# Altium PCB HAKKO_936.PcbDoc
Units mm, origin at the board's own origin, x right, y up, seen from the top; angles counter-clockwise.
Board outline 100 x 73 mm, 2 copper layers (Top Layer, Bottom Layer); 42 components, 27 nets, 110 pads, 10 vias.
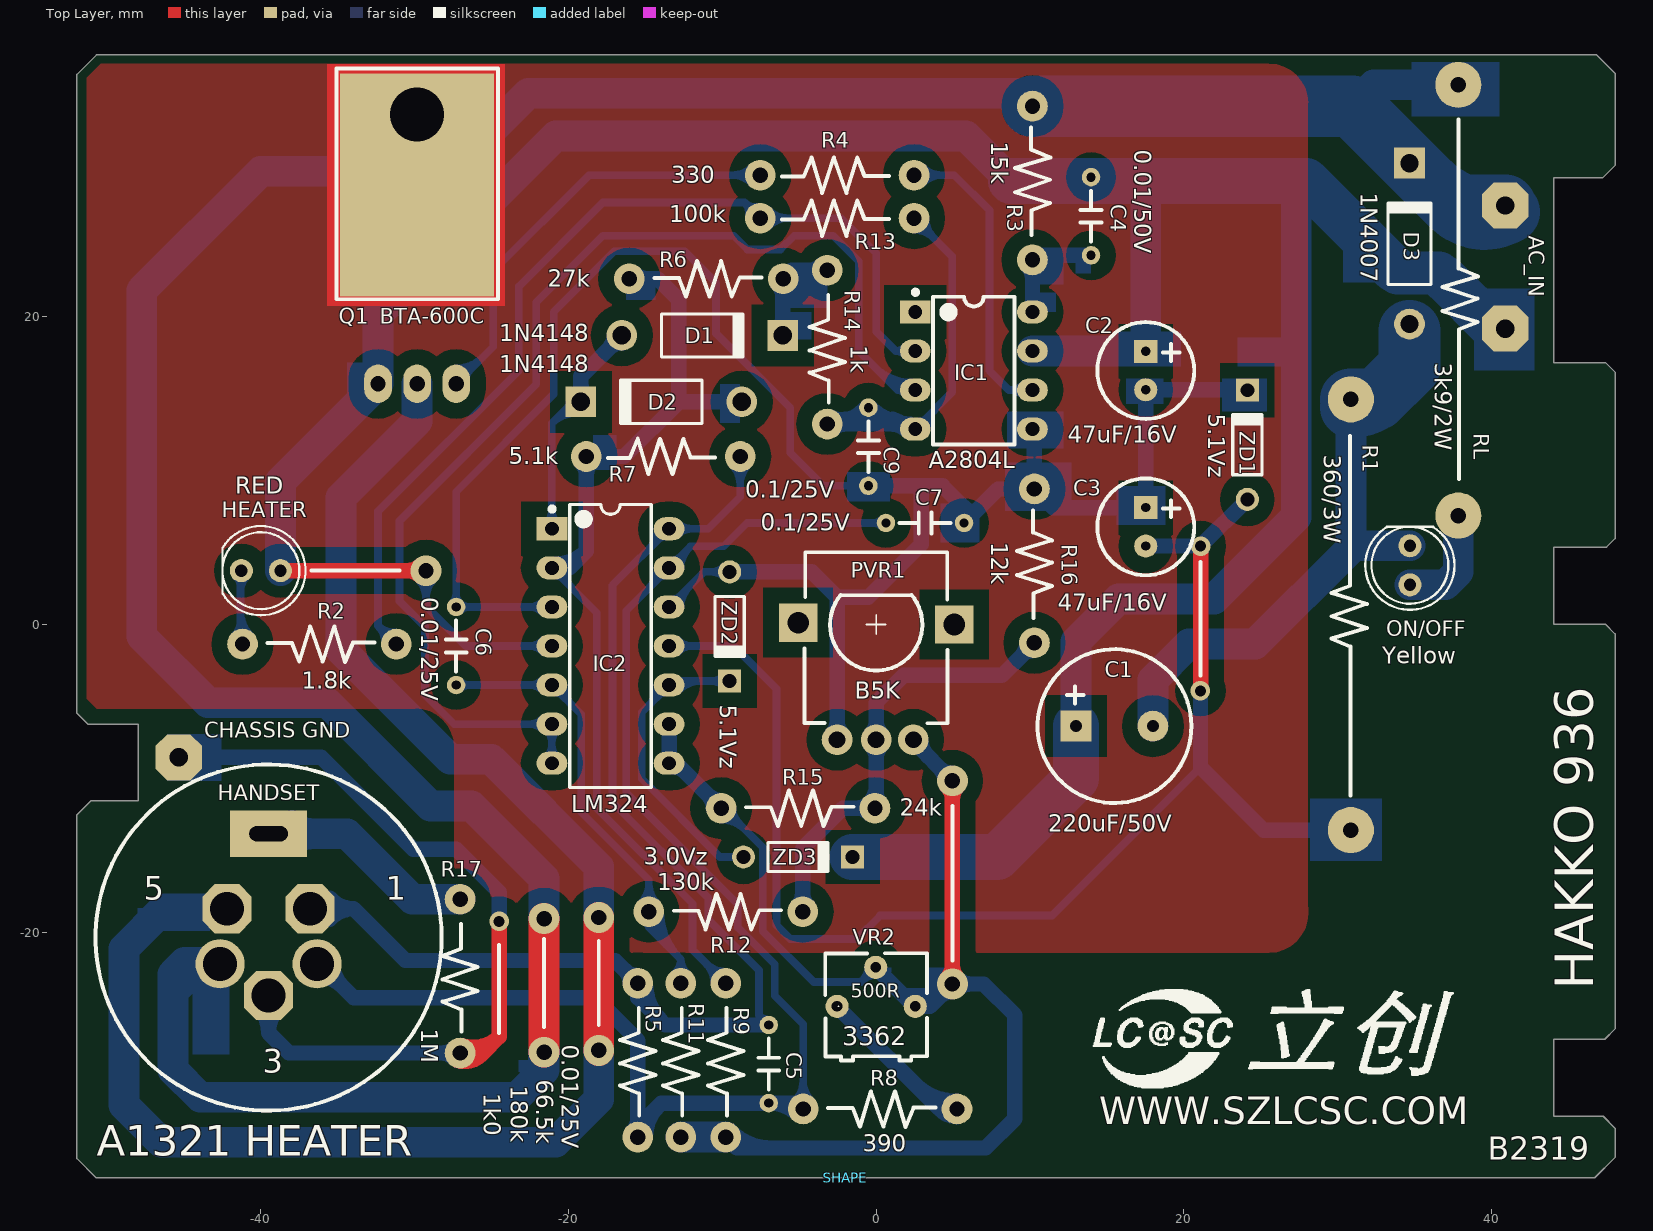
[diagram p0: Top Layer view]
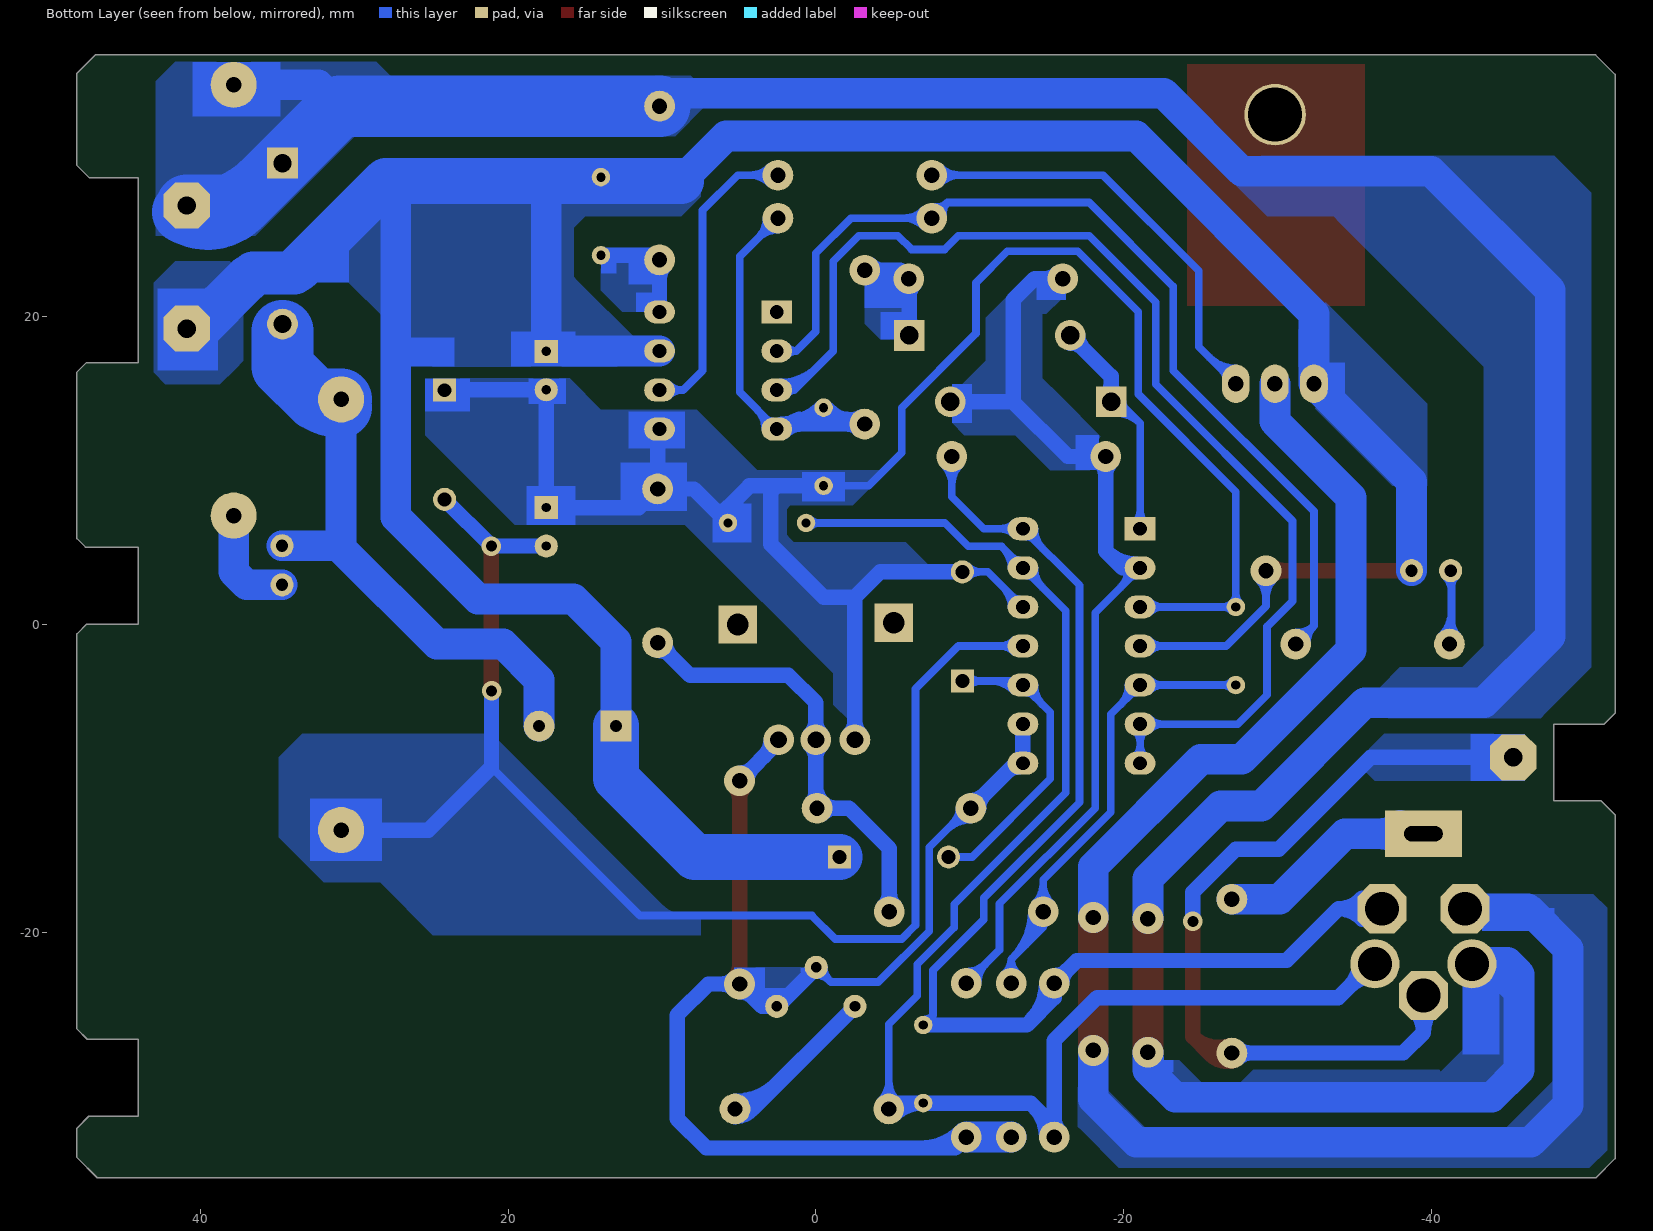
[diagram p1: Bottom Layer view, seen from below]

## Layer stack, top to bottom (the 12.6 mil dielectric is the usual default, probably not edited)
Top Layer: signal copper 0.0356
Dielectric: dielectric 0.32, FR-4, Dk 4.8
Bottom Layer: signal copper 0.0356

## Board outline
-51.962,-34.724 -51.962,-12.372 -51.059,-11.469 -47.962,-11.469 -47.962,-6.469 -51.261,-6.469 -51.962,-5.768 -51.962,35.761 -50.692,37.031 46.844,37.031 48.038,35.837 48.038,29.843 47.226,29.031 44.038,29.031 44.038,17.031 47.413,17.031 48.038,16.406 48.038,5.586 47.483,5.031 44.038,5.031 44.038,0.031 47.395,0.031 48.038,-0.612 48.038,-26.291 47.36,-26.969 44.038,-26.969 44.038,-31.969 47.264,-31.969 48.038,-32.743 48.038,-34.648 46.717,-35.969 -50.717,-35.969

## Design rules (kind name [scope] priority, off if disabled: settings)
Clearance Clearance_1 [InPolygon] p1 off: gap=1
Clearance [All] p2: gap=0.254
ComponentClearance [All] p1 off: gap=0.254 collisioncheckmode=3 verticalgap=0.254 showdistances=FALSE
Height [All] p1 off: minheight=0 maxheight=25.4 prefheight=12.7
PolygonConnect [All] p1: connectstyle=Relief reliefconductorwidth=0.254 reliefentries=4 polygonreliefangle="90 Angle" airgapwidth=0.254
RoutingVias [All] p1: holewidth=0.711 width=1.27 viastyle="Through Hole" minholewidth=0.711 minwidth=1.27 maxholewidth=3 maxwidth=5
SolderMaskExpansion [All] p1: expansion=0.102
Width [All] p1: maxlimit=10 minlimit=0.254 preferedwidth=0.254
26 further rules are at their usual default settings.

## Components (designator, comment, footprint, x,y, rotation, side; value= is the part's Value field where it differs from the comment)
AC_IN "24VAC" AC_IN 40.894,23.241 r270 top
C1 "220uF/50V" CAP_POL_5mm 15.494,-6.604 r0 top
C2 "47uF/16V" CAP_POL_2.5mm 17.526,16.51 r270 top
C3 "47uF/16V" CAP_POL_2.5mm 17.526,6.35 r270 top
C4 "0.01uF/50V" CAP_5.05mm 13.97,26.543 r270 top
C5 "0.01uF/25V" CAP_5.05mm -6.985,-28.575 r270 top
C6 "0.01uF/25V" CAP_5.05mm -27.305,-1.397 r270 top
C7 "0.1uF/25V" CAP_5.05mm 3.175,6.604 r180 top
C9 "0.01uF/25V" CAP_5.05mm -0.508,11.557 r90 top
"CHASSIS GND" "CHASSIS GND" CHASSIS_GND -45.339,-8.636 r90 top
D1 "1N4148" DO-41 -11.303,18.796 r0 top
D2 "1N4148" DO-41 -13.97,14.478 r180 top
D3 "1N4007" DO-41 34.671,24.765 r90 top
HANDSET "HANDSET SOCKET" "HANDSET - metal" -39.5,-20.35 r0 top
HEATER "LED_RED" LED -40,3.5 r180 top locked
IC1 "uPC1701C/KA2804" uPC1701C 6.35,16.51 r0 top
IC2 "uPC324" UPC324C -17.272,-1.397 r0 top
ON/OFF "LED_RED" LED 34.7,3.85 r90 top locked
PVR1 "TEMP CTRL" RK09L1140A65 0,0 r0 top locked
Q1 "NEC AC05D 5A TRIAC" TRIAC -29.845,33.147 r0 top locked
R1 "360/5W" RES_2W 30.861,0.635 r90 top
R2 "1K8" RES_1/4W -36.195,-1.27 r180 top
R3 "15K" RES_1/4W 10.16,28.702 r270 top
R4 "330" RES_1/4W -2.54,29.21 r0 top
R5 "1K0 1%" RES_1/4W -15.494,-28.321 r90 top
R6 "27K 1%" RES_1/4W -11.049,22.479 r180 top
R7 "5K1 1%" RES_1/4W -13.843,10.922 r0 top
R8 "390 1%" RES_1/4W 0.254,-31.496 r180 top
R9 "66K5 1%" RES_1/4W -9.779,-28.321 r90 top
R11 "180K 1%" RES_1/4W -12.7,-28.321 r90 top
R12 "130K 1%" RES_1/4W -9.779,-18.669 r180 top
R13 "100K" RES_1/4W -2.54,26.416 r0 top
R14 "1K0" RES_1/4W -3.175,18.034 r90 top
R15 "24K0" RES_1/4W -5.08,-11.938 r180 top
R16 "1K2" RES_1/4W 10.287,3.81 r270 top
R17 "1M0 5%" RES_1/4W -27.051,-22.86 r90 top
RL "3K9 2W" RES_2W 37.846,21.082 r270 top
SHAPE "Comment" BOARD_SHAPE -2,-35.969 r0 top locked
VR2 "CALCTRL" Bournes_3362P 0,-24.9 r0 top locked
ZD1 "5.1Vz 500mW" DO-35 24.13,11.684 r90 top
ZD2 "5.1Vz 500mW" DO-35 -9.525,-0.127 r270 top
ZD3 "3.0Vz 500mW" DO-35 -5.08,-15.113 r0 top

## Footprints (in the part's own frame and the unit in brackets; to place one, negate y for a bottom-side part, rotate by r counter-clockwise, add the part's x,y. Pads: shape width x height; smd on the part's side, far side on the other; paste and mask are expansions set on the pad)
AC_IN [mm]
  oct 3x3 hole 1.2: 1(-4,0) 2(4,0)
BOARD_SHAPE [mm]
Bournes_3362P [mm]
  round 1.5 hole 0.7: 1(2.54,0.076) 2(-2.54,0.076) 3(-0.03,2.612)
  silkscreen extent -3.31,-3.45 3.3,3.53, body extent -3.3,-3.45 3.3,3.53, height 4.7
CAP_5.05mm [mm] "0.1uF 25V"
  round 1.2 hole 0.6: 1(-2.54,0) 2(2.54,0)
  silkscreen extent -1.65,-0.68 1.65,0.68
CAP_POL_2.5mm [mm]
  rect 1.5x1.5 hole 0.6: 1(-1.25,0)
  round 1.5 hole 0.6: 2(1.25,0)
  silkscreen extent -3.15,-3.15 3.15,3.15
CAP_POL_5mm [mm]
  rect 2x2 hole 0.8: 1(-2.5,0)
  round 2 hole 0.8: 2(2.5,0)
  silkscreen extent -5,-5 5,5
CHASSIS_GND [mm]
  oct 3x3 hole 1.2: 1(0,0)
DO-35 [mm] "Diode, Axial; Body 3.8 x 1.9 mm (LxDia. max), Lead Dia. 0.53 mm (max)"
  round 1.5 hole 0.9: A(-3.55,0)
  rect 1.5x1.5 hole 0.9: K(3.55,0)
  silkscreen extent -1.95,-0.95 2.05,0.95
DO-41 [mm] "Diode, Axial; Body 5.2 x 2.7 mm (LxDia. max), Lead Dia. 0.86 mm (max)"
  round 2 hole 1.2: A(-5.23,0)
  rect 2x2 hole 1.2: K(5.23,0)
  silkscreen extent -2.65,-1.4 2.75,1.4
"HANDSET - metal" [mm]
  oct 3.2x3.2 hole 2.2: 1(2.7,1.875) 3(0,-3.77) 5(-2.7,1.875)
  round 3.2 hole 2.2: 2(3.15,-1.71) 4(-3.15,-1.71)
  rect 5x3 hole 1 slot 2.5 at 0 deg: 6(0,6.75)
  silkscreen extent -11.25,-11.25 11.25,11.25
LED [mm]
  round 1.5 hole 0.8: A(-1.27,0) K(1.27,0)
  silkscreen extent -2.9,-2.9 2.5,2.9
RES_1/4W [mm]
  round 2 hole 1: 1(5,0) 2(-5,0)
  silkscreen extent -3.6,-1.15 3.38,1.16
RES_2W [mm]
  round 3 hole 1: 1(-14,0) 2(14,0)
  silkscreen extent -11.74,-1.04 11.61,1.27
RK09L1140A65 [mm]
  round 2 hole 1.1: 1(2.413,-7.493) 2(-2.54,-7.493) 3(0,-7.493)
  rect 2.5x2.5 hole 1.4: 4(-5.08,0.127) 4(5.08,0)
  silkscreen extent -4.66,-6.42 4.64,4.7, body extent -6.05,-7.65 6.05,4.85, height 35
TRIAC [mm]
  round 4 hole 3.5 unplated: 0(-0.01,0)
  rect 10x14.5 smd: 0(0,-4.56)
  oval 1.8x2.5 hole 1: G(2.54,-17.5) T1(-2.54,-17.5) T2(0,-17.5)
  silkscreen extent -5.25,-12 5.25,3
UPC324C [mm]
  rect 2x1.5 hole 0.9: 1(-3.81,7.62)
  oval 2x1.5 hole 0.9: 2(-3.81,5.08) 3(-3.81,2.54) 4(-3.81,0) 5(-3.81,-2.54) 6(-3.81,-5.08) 7(-3.81,-7.62) 8(3.81,-7.62) 9(3.81,-5.08) 10(3.81,-2.54) 11(3.81,0) 12(3.81,2.54) 13(3.81,5.08) 14(3.81,7.62)
  silkscreen extent -3.95,-9.2 2.65,9.2, body extent -3.94,-9.52 3.94,9.53, height 4.19
uPC1701C [mm]
  rect 2x1.5 hole 0.9: 1(-3.81,3.81)
  oval 2x1.5 hole 0.9: 2(-3.81,1.27) 3(-3.81,-1.27) 4(-3.81,-3.81) 5(3.81,-3.81) 6(3.81,-1.27) 7(3.81,1.27) 8(3.81,3.81)
  silkscreen extent -3.95,-4.8 2.65,5.24, body extent -3.93,-5.46 3.94,5.46, height 5.08

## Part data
AC_IN: library part 24VAC_IN, "POWER"
C1 C2 C3: library part "Cap Pol1", "Polarized Capacitor (Radial)"
C4 C5 C6 C7 C9: library part Cap, "Capacitor"
D1 D2 D3: library part Diode, "Default Diode"
HEATER ON/OFF: library part LED1, "Typical RED GaAs LED"
IC1: library part uPC1701C, "TRIAC DRIVER"
IC2: "Quar Amplifier"
PVR1 VR2: library part RPot, "Potentiometer"
Q1: library part Triac, "Silicon Bidirectional Triode Thyristor"
R1 R2 R3 R4 R5 R6 R7 R8 R9 R11 R12 R13 R14 R15 R16 R17 RL: library part "Res Semi", "Semiconductor Resistor"
ZD1 ZD2 ZD3: library part "D Zener", "Zener Diode"

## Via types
v1: diameter 2, hole 1, Top Layer to Bottom Layer, 7 vias
v2: diameter 1.27, hole 0.711, Top Layer to Bottom Layer, 3 vias

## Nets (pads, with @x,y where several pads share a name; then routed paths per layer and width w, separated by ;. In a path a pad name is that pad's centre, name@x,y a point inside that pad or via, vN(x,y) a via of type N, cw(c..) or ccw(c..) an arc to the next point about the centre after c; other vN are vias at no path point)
CHASSIS_GND: "CHASSIS GND.1" HANDSET.3 R17.2 | length 67.9
  Top Layer w1: R17.2@-27.201,-28.337 ccw(c-26.747,-26.894) -25.678,-27.964 ; R17.2 -25.574,-27.86 -24.511,-26.797 ; R17.2@-26.901,-27.383 ccw(c-26.189,-25.119) -24.511,-26.797 ; R17.2@-26.697,-28.214 cw(c-25.844,-29.067) -25.844,-27.86 cw(c-25.844,-26.653) R17.2@-26.697,-27.506 ; v2(-24.511,-19.304) -24.511,-26.797
  Bottom Layer w1: -45.339,-8.636 -36.068,-8.636 -30.099,-14.605 -27.305,-14.605 -24.511,-17.399 v2(-24.511,-19.304) ; -44.632,-9.343 cw(c-42.925,-11.05) -42.925,-8.636 cw(c-42.925,-6.222) -44.632,-7.929 ; HANDSET.3@-40.207,-24.807 cw(c-41.914,-26.514) -39.5,-26.514 cw(c-37.086,-26.514) HANDSET.3@-38.793,-24.807 ; HANDSET.3@-39.5,-24.1 -39.5,-26.54 -38.18,-27.86 R17.2 ; R17.2@-27.405,-28.214 ccw(c-28.258,-29.067) -28.258,-27.86 ccw(c-28.258,-26.653) R17.2@-27.405,-27.506
"CKT GND": C2.2 C3.1 C6.1 C7.1 C9.1 IC1.5 IC2.3 IC2.12 PVR1.2 R16.2 ZD1.K ZD2.A | length 152.1
  Bottom Layer w0.5: C6.1@-27.552,1.39 ccw(c-28.15,1.988) -27.305,1.988 ccw(c-26.46,1.988) -27.058,1.39 ccw(c-26.46,1.988) -26.46,1.143 ccw(c-26.46,0.298) C6.1@-27.058,0.896 ; IC2.3@-21.686,0.789 ccw(c-22.539,-0.064) -22.539,1.143 ccw(c-22.539,2.35) IC2.3@-21.686,1.497 ; IC2.3 C6.1 -27.305,8.636 -20.955,14.986 -20.955,20.32 -17.018,24.257 -12.446,24.257 -10.414,22.225 -10.414,18.923 -5.588,14.097 -5.588,11.176 -3.429,9.017 C9.1 ; IC2.12 -11.182,3.423 ZD2.A ; IC2.12@-13.212,1.643 ccw(c-13.212,2.247) -12.785,1.82 ; IC2.12@-12.712,1.143 cw(c-10.901,1.143) -12.182,2.423 ; ZD2.A@-9.879,3.069 ccw(c-10.732,2.216) -10.732,3.423 ccw(c-10.732,4.63) ZD2.A@-9.879,3.777 ; C9.1@-0.755,8.77 ccw(c-1.353,8.172) -1.353,9.017 ccw(c-1.353,9.862) C9.1@-0.755,9.264
  Bottom Layer w1: ZD2.A -4.185,3.423 -2.54,1.778 ; PVR1.2@-2.894,-7.139 ccw(c-3.747,-6.286) -2.54,-6.286 ccw(c-1.333,-6.286) PVR1.2@-2.186,-7.139 ; PVR1.2 -2.54,1.778 ; C9.1 2.794,9.017 ; 4.826,8.509 cw(c2.921,6.604) C7.1@5.615,6.604 ; R16.2@9.933,8.456 ccw(c9.08,7.603) 9.08,8.81 ccw(c9.08,10.017) 9.933,9.164 ccw(c9.08,10.017) 10.287,10.017 ccw(c11.494,10.017) R16.2@10.641,9.164 ; IC1.5 10.287,12.573 R16.2 ; R16.2@10.287,8.31 cw(c10.287,7.103) 11.141,7.956 cw(c11.994,8.81) R16.2@10.787,8.81 ; 10.287,11.799 cw(c11.311,11.799) IC1.5@10.587,12.523 ; ZD1.K 24.104,15.26 C2.2 C3.1 11.497,7.6 R16.2 ; -2.54,1.778 -0.508,1.778 2.921,5.207 2.921,8.636 2.794,8.763 2.794,9.017 ; 2.794,9.017 4.318,9.017 5.715,7.62 C7.1 7.921,8.81 R16.2
HEATER1: HANDSET.5 Q1.T2 | length 107.5
  Top Layer w2: v1(-18.034,-27.686) v1(-18.034,-19.05)
  Bottom Layer w2: HANDSET.5@-42.748,-18.475 -46.288,-18.475 -48.895,-21.082 -48.895,-31.242 -46.482,-33.655 -20.828,-33.655 -18.034,-30.861 v1(-18.034,-27.686) ; Q1.T2 -29.845,13.208 -34.798,8.255 -34.798,-1.651 -27.686,-8.763 -25.019,-8.763 -18.034,-15.748 v1(-18.034,-19.05)
HEATER2: AC_IN.1 D3.K HANDSET.4 R3.2 RL.1 | length 224.1
  Top Layer w2: v1(-21.59,-27.813) v1(-21.59,-19.117)
  Bottom Layer w2: -45.259,-23.415 cw(c-42.748,-25.927) HANDSET.4@-42.748,-22.375 ; HANDSET.4@-42.748,-21.975 -44.962,-21.975 -45.72,-22.733 -45.72,-28.956 -43.942,-30.734 -23.368,-30.734 -21.59,-28.956 v1(-21.59,-27.813) cw(c-24.349,-27.813) -22.398,-29.764 ; v1(-21.59,-19.117) -21.59,-16.51 -26.304,-11.796 -28.971,-11.796 -35.687,-5.08 -43.434,-5.08 -47.752,-0.762 -47.752,21.717 -40.005,29.464 -27.686,29.464 -22.606,34.544 9.318,34.544 R3.2 ccw(c8.127,31.669) 8.127,34.544 ; 30.964,33.702 32.344,35.082 RL.1
  Bottom Layer w4: R3.2 30.964,33.702 D3.K 37.425,27.241 ; 35.826,28.84 ccw(c40.894,33.909) AC_IN.1@40.894,26.741 ; AC_IN.1 37.425,27.241 ; AC_IN.1@41.159,26.817 cw(c39.558,29.374) 37.425,27.241
NetC1_2: C1.2 D3.A ON/OFF.K R1.2 | length 41.9
  Bottom Layer w2: C1.2 17.994,-3.596 20.32,-1.27 24.638,-1.27 30.861,4.953 ; 30.861,5.12 R1.2 ; 31.028,5.12 ON/OFF.K
  Bottom Layer w4: R1.2@30.861,14.135 ccw(c30.861,16.986) 32.877,14.97 ; R1.2 32.542,14.635 34.671,16.764 D3.A@34.671,19.106
NetC4_2: C4.2 IC1.8 R3.1 | length 11
  Bottom Layer w1: R3.1@9.806,23.348 cw(c8.953,22.495) 10.16,22.495 cw(c11.367,22.495) 10.514,23.348 cw(c12.094,21.768) 12.094,24.003 ; IC1.8 R3.1 10.461,24.003 C4.2
NetC6_2: C6.2 IC2.5 R11.1 R12.1 | length 47.3
  Bottom Layer w0.5: C6.2 IC2.5 -19.177,-5.842 -19.177,-12.192 -14.779,-16.59 -14.779,-19.685 ; C6.2@-27.058,-4.184 cw(c-26.46,-4.782) -26.46,-3.937 cw(c-26.46,-3.092) C6.2@-27.058,-3.69 ; IC2.5@-21.686,-4.291 ccw(c-22.539,-5.144) -22.539,-3.937 ccw(c-22.539,-2.73) IC2.5@-21.686,-3.583 ; IC2.5@-20.832,-4.437 cw(c-20.832,-5.041) -20.405,-4.614 ; IC2.5@-20.332,-3.937 ccw(c-18.521,-3.937) -19.802,-5.217 ; R12.1@-15.309,-18.139 ccw(c-16.59,-16.858) -14.779,-16.858 ccw(c-12.968,-16.858) R12.1@-14.249,-18.139 ; R12.1@-15.029,-18.669 ccw(c-13.18,-18.669) -14.487,-19.977 ; R12.1@-15,-19.386 cw(c-15.092,-19.685) -14.779,-19.685 ; R12.1@-14.558,-19.386 ccw(c-14.466,-19.685) -14.779,-19.685 ; R12.1@-14.529,-18.669 ccw(c-11.473,-18.669) -13.634,-20.83 ; R12.1@-14.029,-18.669 ccw(c-9.765,-18.669) -12.78,-21.684 ; R11.1@-13.167,-22.735 ccw(c-13.941,-21.764) -12.7,-21.764 ; R11.1 -12.7,-21.764 ; R11.1@-12.233,-22.735 cw(c-11.459,-21.764) -12.7,-21.764 ; -14.779,-19.685 -12.7,-21.764
NetC9_2: C9.2 IC1.4 R13.1 R14.2 | length 39.7
  Bottom Layer w0.5: R13.1@2.46,25.666 cw(c2.46,23.855) 3.74,25.136 cw(c5.021,26.416) R13.1@3.21,26.416 ; R13.1 4.953,23.923 4.953,15.113 IC1.4 ; IC1.4@2.79,13.2 ccw(c2.79,13.804) 3.217,13.377 ; IC1.4@3.29,12.7 cw(c5.101,12.7) 3.82,13.98
  Bottom Layer w1: R14.2@-2.925,13.467 ccw(c-2.321,14.512) -2.009,13.346 ccw(c-1.697,12.18) R14.2@-2.742,12.784 ; R14.2@-2.821,12.68 cw(c-1.968,11.827) -1.968,13.034 cw(c-1.968,14.241) R14.2@-2.821,13.388 ; C9.2@-0.581,14.165 cw(c-3.175,16.573) R14.2 -0.508,13.034 ; C9.2 -0.508,13.034 ; C9.2@-0.436,14.166 ccw(c2.206,16.682) IC1.4@2.206,13.034 ; 0.88,13.034 cw(c0.88,11.29) IC1.4@2.113,12.523 ; 1.083,13.335 cw(c0.661,11.76) IC1.4@2.073,12.575 ; IC1.4 IC1.4@2.206,13.034 ; -0.508,13.034 IC1.4@2.206,13.034
NetD1_A: D1.A D2.K IC2.1 | length 24.1
  Bottom Layer w0.5: IC2.1@-21.436,6.577 ccw(c-22.289,7.43) -21.082,7.43 ccw(c-19.875,7.43) IC2.1@-20.728,6.577 ; IC2.1 -21.082,13.081 ; -20.332,13.831 cw(c-19.356,12.855) D2.K@-19.224,14.229 ; D2.K@-20.137,14.026 ccw(c-20.59,14.478) D2.K@-19.95,14.478 ; D2.K@-19.272,13.731 ccw(c-19.487,11.486) -21.082,13.081 ; D2.K -19.685,14.478 -21.082,13.081
  Bottom Layer w1: D2.K@-19.554,14.832 ccw(c-20.407,15.685) -19.2,15.685 ccw(c-17.993,15.685) D2.K@-18.846,14.832 ; D2.K -19.2,16.129 D1.A ; D1.A@-17.033,18.796 cw(c-18.24,18.796) -17.387,17.942 cw(c-16.533,17.089) D1.A@-16.533,18.296
NetD1_K: D1.K R6.2 R14.1 | length 14.9
  Bottom Layer w1: D1.K@-6.427,19.15 ccw(c-7.28,20.003) -6.073,20.003 ccw(c-4.866,20.003) D1.K@-5.719,19.15 ; R6.2@-6.403,22.125 cw(c-7.198,21.33) -6.073,21.33 ; D1.K -6.073,22.455 R6.2 -5.494,23.034 R14.1 ; -6.073,21.214 cw(c-4.784,21.214) -5.695,22.125 cw(c-3.502,19.932) R14.1@-3.502,23.034 ; R14.1@-3.529,22.68 ccw(c-4.382,21.827) -4.382,23.034 ccw(c-4.382,24.241) R14.1@-3.529,23.388
NetD2_A: D2.A IC2.2 R6.1 R7.2 R9.1 | length 77
  Bottom Layer w0.5: IC2.2 -18.161,0.762 -18.161,-11.938 -11.938,-18.161 -11.938,-21.162 R9.1 ; IC2.2@-20.832,3.183 cw(c-20.832,2.579) -20.405,3.006 ; IC2.2@-20.332,3.683 ccw(c-18.521,3.683) -19.802,2.403 ; R9.1@-10.529,-23.321 ccw(c-12.34,-23.321) -11.059,-22.041 ccw(c-9.779,-20.76) R9.1@-9.779,-22.571
  Bottom Layer w1: IC2.2 -19.939,3.683 -18.843,4.779 R7.2 -16.383,10.922 -12.827,14.478 ; IC2.2@-20.832,3.933 ccw(c-20.832,6.692) -18.881,4.741 ; R7.2@-19.197,10.568 cw(c-20.05,9.715) -18.843,9.715 cw(c-17.636,9.715) -18.489,10.568 cw(c-17.636,9.715) -17.636,10.922 cw(c-17.636,12.129) R7.2@-18.489,11.276 ; R6.1 -14.224,22.479 -12.827,21.082 -12.827,14.478 ; R6.1@-15.695,22.125 cw(c-14.842,21.272) -14.842,22.479 cw(c-14.842,23.686) R6.1@-15.695,22.833 ; D2.A@-9.094,14.124 ccw(c-9.947,13.271) -9.947,14.478 ccw(c-9.947,15.685) D2.A@-9.094,14.832 ; D2.A -12.827,14.478
NetHANDSET_6: HANDSET.6 R17.1 | length 17.1
  Bottom Layer w2: HANDSET.6 -34.406,-13.6 -30.146,-17.86 R17.1 ; HANDSET.6@-37.97,-14.13 cw(c-36.689,-15.411) -36.689,-13.6 cw(c-36.689,-11.789) HANDSET.6@-37.97,-13.07
NetHEATER_K: HEATER.K R2.1 | length 9.5
  Top Layer w0.5: HEATER.K HEATER.K@-41.195,3.425
  Bottom Layer w0.5: R2.1@-41.725,-0.74 ccw(c-42.699,0.234) -41.322,0.234 ; HEATER.K@-41.624,3.146 cw(c-42.352,2.418) -41.322,2.418 ; R2.1@-41.322,-1.27 HEATER.K@-41.322,3.425 ; -41.322,0.847 ccw(c-39.078,0.847) R2.1@-40.665,-0.74 ; -41.322,2.167 cw(c-39.937,2.167) HEATER.K@-40.916,3.146
NetIC1_2: IC1.2 R2.2 R13.2 | length 71.3
  Bottom Layer w0.5: R2.2@-31.944,-1.23 ccw(c-33.455,-1.15) -32.385,-0.08 ; R2.2@-31.235,-0.521 cw(c-31.315,0.99) -32.385,-0.08 ; R2.2 -32.385,-0.08 ; R13.2@-8.278,26.548 ccw(c-9.264,26.724) -8.556,27.432 ; R13.2@-7.672,27.154 cw(c-7.848,28.14) -8.556,27.432 ; R13.2@-7.01,25.886 cw(c-5.729,24.605) -5.729,26.416 cw(c-5.729,28.227) R13.2@-7.01,26.946 ; IC1.2@1.895,17.474 ccw(c1.27,16.99) 1.27,17.78 ; IC1.2@1.895,18.086 cw(c1.27,18.57) 1.27,17.78 ; IC1.2 1.27,17.78 ; -32.385,-0.08 -32.385,7.366 -23.241,16.51 -23.241,21.971 -17.78,27.432 -8.556,27.432 ; -8.556,27.432 R13.2 -2.286,26.416 0,24.13 0,19.05 1.27,17.78
NetIC1_3: IC1.3 IC2.6 IC2.7 | length 87.4
  Bottom Layer w0.5: IC2.6@-21.686,-6.831 ccw(c-22.539,-7.684) -22.539,-6.477 ccw(c-22.539,-5.27) IC2.6@-21.686,-6.123 ; IC2.7@-21.436,-8.663 ccw(c-22.289,-7.81) -21.082,-7.81 ccw(c-19.875,-7.81) IC2.7@-20.728,-8.663 ; IC2.6@-21.436,-6.831 cw(c-22.289,-7.684) -21.082,-7.684 cw(c-19.875,-7.684) IC2.6@-20.728,-6.831 ; IC2.7 IC2.6 -27.432,-6.477 -29.337,-4.572 -29.337,-0.127 -30.988,1.524 -30.988,6.731 -22.098,15.621 -22.098,20.955 -17.78,25.273 -9.271,25.273 -8.382,24.384 -6.223,24.384 -5.334,25.273 -2.794,25.273 -1.143,23.622 -1.143,17.78 1.397,15.24 ; -0.088,16.725 ccw(c2.29,19.103) IC1.3@2.29,15.74 ; 0.766,15.871 ccw(c2.29,17.396) IC1.3@2.29,15.24 ; IC1.3@1.864,14.979 ccw(c1.397,14.693) 1.397,15.24 ; IC1.3@1.864,15.501 cw(c1.397,15.787) 1.397,15.24 ; IC1.3 1.397,15.24
NetIC1_6: IC1.6 R4.1 | length 24.3
  Bottom Layer w0.5: R4.1 5.08,29.21 7.366,26.924 7.366,16.51 8.636,15.24 IC1.6 ; R4.1@2.99,28.68 cw(c4.271,27.399) 4.271,29.21 cw(c4.271,31.021) R4.1@2.99,29.74 ; IC1.6@9.556,14.886 ccw(c8.703,14.033) 8.703,15.24 ccw(c8.703,16.447) IC1.6@9.556,15.594
NetIC2_10: IC2.10 ZD2.K ZD3.A | length 25
  Bottom Layer w0.5: -14.742,-5.217 ccw(c-16.023,-3.937) IC2.10@-14.212,-3.937 ; -14.139,-4.614 cw(c-13.712,-5.041) IC2.10@-13.712,-4.437 ; IC2.10@-12.858,-4.291 cw(c-11.377,-5.772) -11.377,-3.677 ; ZD2.K@-9.879,-4.031 ccw(c-10.732,-4.884) -10.732,-3.677 ccw(c-10.732,-2.47) ZD2.K@-9.879,-3.323 ; ZD2.K -13.202,-3.677 IC2.10 -15.24,-5.715 -15.24,-10.033 -10.16,-15.113 ZD3.A
NetON/OFF_A: ON/OFF.A RL.2 | length 7.2
  Bottom Layer w2: ON/OFF.A 36.997,2.58 37.846,3.429 RL.2
NetPVR1_3: PVR1.3 R12.2 R15.2 R16.1 | length 40.1
  Bottom Layer w1: R12.2@-5.133,-18.315 ccw(c-5.986,-17.462) -4.779,-17.462 ccw(c-3.572,-17.462) R12.2@-4.425,-18.315 ; R12.2 -4.779,-14.558 -2.159,-11.938 R15.2 0,-11.858 PVR1.3 0,-5.08 1.778,-3.302 8.175,-3.302 R16.1 ; R15.2@-0.434,-12.292 ccw(c-1.287,-13.145) -1.287,-11.938 ccw(c-1.287,-10.731) -0.434,-11.584 ccw(c-1.48,-10.538) 0,-10.538 ; PVR1.3@-0.354,-7.847 cw(c-1.207,-8.7) 0,-8.7 cw(c1.207,-8.7) PVR1.3@0.354,-7.847 ; PVR1.3@-0.354,-7.139 ccw(c-1.207,-6.286) 0,-6.286 ccw(c1.207,-6.286) PVR1.3@0.354,-7.139 ; 0,-10.924 ccw(c0.934,-10.924) R15.2@0.274,-11.584 ; R16.1@9.787,-1.19 cw(c8.58,-1.19) 9.433,-2.044 cw(c10.287,-2.897) R16.1@10.287,-1.69
NetQ1_G: Q1.G R4.2 | length 34.5
  Bottom Layer w0.5: Q1.G -24.892,18.06 -24.892,22.987 -18.669,29.21 R4.2 ; Q1.G@-27.305,16.147 ccw(c-27.305,17.354) -26.451,16.501 ; Q1.G@-27.305,16.647 ccw(c-27.305,19.061) -25.598,17.354 ; Q1.G@-26.655,15.997 cw(c-25.931,15.997) -26.443,16.509 ; R4.2@-8.07,28.68 ccw(c-9.351,27.399) -9.351,29.21 ccw(c-9.351,31.021) R4.2@-8.07,29.74
NetR8_2: R8.2 VR2.2 | length 16.5
  Bottom Layer w1: VR2.2 4.132,-31.496 ; 2.485,-29.849 ccw(c5.254,-27.08) R8.2@5.254,-30.996 ; 4.192,-31.556 ccw(c5.254,-30.494) R8.2@5.254,-31.996 ; R8.2@4.882,-31.83 ccw(c4.132,-32.505) 4.132,-31.496 ; R8.2@4.882,-31.162 cw(c4.132,-30.487) 4.132,-31.496 ; R8.2 4.132,-31.496
SENSOR1: C5.1 HANDSET.1 IC2.14 R5.1 R7.1 | length 95.1
  Bottom Layer w0.5: -14.742,4.943 ccw(c-16.023,6.223) IC2.14@-14.212,6.223 ; -14.139,5.546 cw(c-13.712,5.119) IC2.14@-13.712,5.723 ; IC2.14@-12.858,5.869 cw(c-12.005,5.016) -12.005,6.223 cw(c-12.005,7.43) IC2.14@-12.858,6.577 ; R7.1@-9.373,10.392 cw(c-10.654,9.111) -8.843,9.111 cw(c-7.032,9.111) R7.1@-8.313,10.392 ; R7.1 -8.843,8.302 -10.922,6.223 IC2.14 -17.145,2.54 -17.145,-11.557 -10.922,-17.78 -10.922,-19.177 -7.62,-22.479 -7.62,-25.4 C5.1 ; C5.1@-7.335,-26.035 ccw(c-8.18,-26.035) -7.582,-25.438 ccw(c-6.985,-24.84) C5.1@-6.985,-25.685
  Bottom Layer w1: HANDSET.1@-36.252,-18.475 -33.976,-18.475 ; HANDSET.1@-35.516,-19.151 cw(c-33.976,-20.566) -33.976,-18.475 ; HANDSET.1@-35.516,-17.799 ccw(c-33.976,-16.384) -33.976,-18.475 ; R5.1@-15.994,-23.321 ccw(c-17.201,-23.321) -16.348,-22.467 ccw(c-15.494,-21.614) R5.1@-15.494,-22.821 ; R5.1@-14.994,-23.321 ccw(c-11.527,-23.321) -13.979,-25.772 ; C5.1 -13.716,-26.035 -15.494,-24.257 R5.1 -16.971,-21.844 -30.607,-21.844 -33.976,-18.475
SENSOR2: C5.2 C7.2 HANDSET.2 IC2.13 R5.2 R8.1 | length 114.6
  Bottom Layer w0.5: -14.742,2.403 ccw(c-16.023,3.683) IC2.13@-14.212,3.683 ; -14.139,3.006 cw(c-13.712,2.579) IC2.13@-13.712,3.183 ; IC2.13@-13.212,4.183 ccw(c-13.212,4.787) -12.785,4.36 ; IC2.13@-12.712,3.683 cw(c-10.901,3.683) -12.182,4.963 ; R8.1@-5.276,-30.966 ccw(c-6.557,-29.685) -4.746,-29.685 ccw(c-2.935,-29.685) R8.1@-4.216,-30.966 ; R8.1 -4.746,-25.988 -6.604,-24.13 -6.604,-22.098 -9.009,-19.693 -9.009,-18.184 -16.256,-10.937 -16.256,0.889 IC2.13 -12.065,5.08 -9.906,5.08 -8.382,6.604 C7.2 ; C7.2@0.388,6.357 ccw(c-0.21,5.759) -0.21,6.604 ccw(c-0.21,7.449) C7.2@0.388,6.851
  Bottom Layer w1: HANDSET.2@-36.252,-22.875 cw(c-36.252,-25.048) -34.716,-23.511 cw(c-33.18,-21.975) HANDSET.2@-35.352,-21.975 ; HANDSET.2@-36.252,-21.975 -33.97,-24.257 -18.288,-24.257 -15.494,-27.051 R5.2@-15.494,-32.639 ; R5.2@-15.848,-32.967 ccw(c-16.701,-32.114) -15.494,-32.114 ccw(c-14.287,-32.114) R5.2@-15.14,-32.967 ; R5.2 R5.2@-15.494,-32.639 ; R5.2@-14.994,-33.321 cw(c-12.14,-33.321) -14.158,-31.303 ; C5.2@-6.873,-31.115 cw(c-6.873,-33.623) R8.1@-5.1,-31.85 ; R8.1 -5.127,-31.115 C5.2 -13.97,-31.115 R5.2@-15.494,-32.639
TIP: Q1.0
VCC: AC_IN.2 C1.1 C2.1 C4.1 HEATER.A IC1.7 IC2.4 Q1.T1 ZD3.K | length 214
  Top Layer w1: HEATER.A v1(-29.266,3.5) ; v1@-29.62,3.146 ccw(c-30.473,2.293) -30.473,3.5 ccw(c-30.473,4.707) v1@-29.62,3.854
  Bottom Layer w0.5: v1@-29.796,2.97 cw(c-31.077,1.689) -29.266,1.689 cw(c-27.455,1.689) v1@-28.736,2.97 ; v1(-29.266,3.5) -29.266,1.199 -26.67,-1.397 IC2.4 ; IC2.4@-21.686,-1.751 ccw(c-22.539,-2.604) -22.539,-1.397 ccw(c-22.539,-0.19) IC2.4@-21.686,-1.043
  Bottom Layer w2: HEATER.A -38.73,9.302 Q1.T1 -32.385,20.193 -20.828,31.75 5.842,31.75 8.763,28.829 ; IC1.7 17.506,17.78 C2.1 17.526,28.702 17.653,28.829 ; C1.1 12.994,-1.103 15.748,1.651 21.971,1.651 27.305,6.985 27.305,28.194 27.94,28.829
  Bottom Layer w2.8: 33.655,23.114 33.909,22.86 36.576,22.86 36.957,22.479
  Bottom Layer w3: ZD3.K 7.874,-15.113 12.994,-9.993 C1.1 ; 8.763,28.829 17.653,28.829 27.94,28.829 33.655,23.114 ; 36.957,22.479 40.195,19.241 AC_IN.2
VEE: C3.2 IC2.11 R1.1 ZD1.A | length 95.5
  Top Layer w1: v2(21.082,-4.318) 21.096,-4.332 v2(21.096,5.1)
  Bottom Layer w0.5: IC2.11 -9.271,-1.397 -6.477,-4.191 -6.477,-19.558 -5.588,-20.447 -1.27,-20.447 0.254,-18.923 11.43,-18.923 21.082,-9.271 ; IC2.11@-12.858,-1.751 cw(c-12.005,-2.604) -12.005,-1.397 cw(c-12.005,-0.19) IC2.11@-12.858,-1.043
  Bottom Layer w1: C3.2 v2(21.096,5.1) ZD1.A ; v2(21.082,-4.318) 21.082,-9.271 25.176,-13.365 R1.1 ; R1.1@30.154,-14.072 ccw(c28.447,-15.779) 28.447,-13.365 ccw(c28.447,-10.951) R1.1@30.154,-12.658
VREF: IC2.8 IC2.9 PVR1.1 R9.2 R11.2 R15.1 VR2.1 VR2.3 | length 108.1
  Top Layer w1: v1@4.599,-23.014 ccw(c3.746,-22.161) 4.953,-22.161 ccw(c6.16,-22.161) v1@5.307,-23.014 ; v1@4.599,-10.514 cw(c3.746,-11.367) 4.953,-11.367 cw(c6.16,-11.367) v1@5.307,-10.514 ; v1(4.953,-23.368) v1(4.953,-10.16)
  Bottom Layer w0.5: R15.1@-10.08,-12.688 cw(c-10.08,-14.919) -8.503,-13.341 ; R15.1 -9.906,-11.938 -7.366,-14.478 -7.366,-19.939 -4.064,-23.241 -0.983,-23.241 VR2.3 ; R15.1@-9.33,-11.938 ccw(c-7.939,-11.938) -8.923,-12.921 ; VR2.3@-0.53,-22.288 cw(c-1.737,-22.288) -0.883,-23.141 cw(c-0.03,-23.995) VR2.3@-0.03,-22.788
  Bottom Layer w1: IC2.9 IC2.8 -13.001,-9.017 R15.1 ; IC2.8@-13.212,-9.267 cw(c-13.212,-10.38) -12.425,-9.593 ; R15.1@-10.58,-11.938 ccw(c-11.787,-11.938) -10.934,-11.084 ccw(c-10.08,-10.231) R15.1@-10.08,-11.438 ; R9.2 -9.064,-34.036 7.112,-34.036 9.017,-32.131 9.017,-25.4 6.985,-23.368 v1(4.953,-23.368) 3.497,-24.824 VR2.1 2.506,-24.824 VR2.3 ; R9.2@-9.425,-32.967 ccw(c-6.846,-30.388) -6.846,-34.036 ; PVR1.1 2.413,-7.62 v1(4.953,-10.16) ; VR2.1@2.54,-24.574 ccw(c2.54,-21.659) v1@4.601,-23.72 ; PVR1.1@2.913,-7.493 ccw(c4.427,-7.493) 3.356,-8.563 ; 3.703,-24.239 ccw(c2.879,-22.812) v1@4.47,-23.239 ; v1@4.453,-23.368 cw(c3.246,-23.368) 4.099,-24.222 cw(c4.953,-25.075) v1@4.953,-23.868 ; v1@4.453,-10.16 ccw(c3.246,-10.16) 4.099,-9.306 ccw(c4.953,-8.453) v1@4.953,-9.66 ; v1@5.307,-23.722 cw(c6.16,-24.575) 6.16,-23.368 cw(c6.16,-22.161) v1@5.307,-23.014
  Bottom Layer w2: R11.2 R9.2
pads on no net: IC1.1 PVR1.4

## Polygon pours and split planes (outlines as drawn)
VREF on Bottom Layer "Bottom Layer-No Net" (solid, pour order 25): -0.03,-22.288 3.873,-22.288 4.953,-23.368 3.497,-24.824 2.506,-24.824 -0.03,-22.288
NetD1_K on Bottom Layer "Bottom Layer-No Net" (solid, pour order 22): -6.073,22.455 -5.494,23.034 -3.175,23.034 -3.175,19.558 -4.191,18.542 -5.819,18.542 -6.073,18.796 -6.049,18.82 -6.049,22.479
NetC4_2 on Bottom Layer "Bottom Layer-No Net" (solid, pour order 19): 10.16,23.702 10.461,24.003 13.97,24.003 13.97,21.717 12.7,20.447 12.573,20.32 10.16,20.32 10.16,23.702
"CKT GND" on Bottom Layer "Bottom Layer-No Net" (solid, pour order 29): 2.032,5.334 -5.842,5.334 -7.62,3.556 -7.112,3.048 -4.699,3.048 -4.191,3.048 -2.54,1.397 -2.54,-6.223 -2.159,-6.223 -1.143,-5.207 -1.143,-3.175 3.302,1.27 2.032,2.54 2.032,5.334
HEATER2 on Bottom Layer "Bottom Layer-No Net" (solid, pour order 34): -43.561,-23.114 -43.561,-26.162 -40.64,-29.083 -40.513,-28.956 -28.575,-28.956 -28.448,-28.956 -27.051,-30.353 -25.654,-30.353 -23.622,-28.321 -22.987,-28.321 -21.463,-29.845 -22.606,-30.988 -44.45,-30.988 -46.101,-29.337 -46.101,-26.67 -46.101,-24.765 -44.577,-23.241 -44.45,-23.114 -43.561,-23.114
HEATER1 on Bottom Layer "Bottom Layer-No Net" (solid, pour order 33): -46.101,-17.526 -50.546,-17.526 -51.435,-18.415 -51.435,-34.163 -50.292,-35.306 -19.685,-35.306 -17.272,-32.893 -17.018,-32.639 -17.018,-30.099 -18.796,-30.099 -18.923,-30.226 -22.098,-33.401 -26.797,-33.401 -44.196,-33.401 -48.641,-28.956 -48.641,-21.209 -46.355,-18.923 -46.101,-18.669 -46.101,-17.526
NetD2_A on Bottom Layer "Bottom Layer-No Net" (solid, pour order 32): -16.049,22.479 -13.589,22.479 -11.811,20.701 -11.049,19.939 -11.049,17.145 -8.509,14.605 -8.509,13.462 -9.652,12.319 -12.954,12.319 -15.24,10.033 -18.923,10.033 -18.796,10.16 -18.796,11.811 -18.796,11.938 -15.875,14.859 -14.732,16.002 -14.732,20.193 -14.986,20.193 -16.129,21.336 -16.049,21.416 -16.049,22.479
VCC on Bottom Layer "Bottom Layer-No Net" (solid, pour order 31): 30.353,24.003 30.353,22.225 28.067,19.939 24.892,16.764 17.145,16.764 12.954,16.764 11.557,18.161 11.557,18.415 15.494,22.352 15.748,22.606 15.748,25.781 14.986,26.543 8.763,26.543 7.493,27.813 7.493,29.972 27.813,29.972 29.591,28.194 30.353,27.432 30.353,24.003
"CKT GND" on Bottom Layer "Bottom Layer-No Net" (solid, pour order 28): -4.191,10.033 3.81,10.033 7.493,13.716 7.747,13.97 11.938,13.97 13.97,13.97 16.002,16.002 19.177,16.002 24.765,16.002 25.4,15.367 25.4,12.319 20.066,6.985 19.558,6.477 10.541,6.477 8.509,6.477 3.683,1.651 3.302,1.27 -0.381,1.27 -0.381,3.556 1.651,5.588 1.905,5.842 1.905,7.493 1.651,7.747 -0.762,7.747 -2.413,7.747 -4.191,9.525 -4.191,10.16
CHASSIS_GND on Bottom Layer "Bottom Layer-No Net" (solid, pour order 26): -46.101,-7.112 -36.957,-7.112 -34.925,-9.144 -35.433,-9.652 -35.814,-9.652 -36.322,-10.16 -45.974,-10.16 -45.974,-7.112
VCC on Bottom Layer "Bottom Layer-No Net" (solid, pour order 24): 37.846,23.622 41.656,23.622 43.053,22.225 43.053,16.383 42.291,15.621 39.751,15.621 38.735,15.621 37.719,16.637 37.211,17.145 37.211,21.336 37.211,22.733 38.1,23.622 38.735,23.622
HEATER2 on Bottom Layer "Bottom Layer-No Net" (solid, pour order 23): 42.926,25.273 42.926,35.306 41.656,36.576 28.575,36.576 25.654,33.655 27.432,31.877 29.845,31.877 36.449,25.273 42.926,25.273
VCC on Bottom Layer "Bottom Layer-No Net" (solid, pour order 21): -33.147,20.955 -39.751,14.351 -39.751,9.017 -37.465,9.017 -32.385,14.097 -31.369,15.113 -31.369,18.923 -31.369,19.177 -33.147,20.955
HEATER2 on Bottom Layer "Bottom Layer-No Net" (solid, pour order 20): -28.067,30.48 -48.006,30.48 -50.419,28.067 -50.419,-2.794 -47.498,-5.715 -47.117,-6.096 -43.434,-6.096 -37.211,-6.096 -36.703,-5.588 -36.703,-4.064 -37.973,-2.794 -42.037,-2.794 -43.434,-1.397 -43.434,16.764 -34.036,26.162 -33.655,26.543 -30.353,26.543 -29.337,26.543 -27.178,28.702 -28.956,30.48 -40.386,30.48
VEE on Bottom Layer "Bottom Layer-No Net" (solid, pour order 18): 21.082,-7.112 10.015,-18.179 cw(c8.219,-16.383) 8.219,-18.923 7.493,-18.923 7.493,-20.193 24.892,-20.193 28.321,-16.764 31.623,-16.764 32.004,-16.764 34.925,-13.843 34.925,-8.636 33.401,-7.112 21.082,-7.112
HEATER2 on Bottom Layer "Bottom Layer-No Net" (solid, pour order 27): 10.668,31.75 9.144,31.75 7.239,33.655 7.239,34.798 8.128,35.687 10.033,35.687 10.414,35.687 11.176,34.925 11.049,34.798 11.049,32.385 11.049,32.131 10.668,31.75
TIP on Top Layer "Bottom Layer-No Net" (solid, pour order 30): -50.419,36.449 25.527,36.449 cw(c25.527,33.909) 28.067,33.909 28.067,-17.907 28.067,-18.796 cw(c25.527,-18.796) 25.527,-21.336 -25.273,-21.336 cw(c-25.273,-19.177) -27.432,-19.177 -27.432,-13.716 -27.432,-8.001 ccw(c-29.972,-8.001) -29.972,-5.461 -47.879,-5.461 -50.673,-5.461 -51.308,-4.826 -51.308,35.56 -50.419,36.449

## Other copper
Top Layer:
  rectangle net TIP: -35.687,20.701 -24.13,36.449
Bottom Layer:
  rectangle net VREF: 1.778,-24.318 3.417,-23.622
  rectangle net VREF: 3.302,-24.096 5.334,-22.288
  rectangle net VREF: 0.127,-22.606 0.983,-22.288
  rectangle net VCC: 30.353,22.225 33.02,24.511
  rectangle net VCC: 23.495,16.764 27.305,18.669
  rectangle net NetD1_K: -6.477,18.542 -4.191,20.32
  rectangle net NetD1_K: -6.049,20.574 -3.175,22.606
  rectangle net NetC4_2: 12.954,22.808 13.97,24.003
  rectangle net NetC4_2: 10.033,20.32 11.684,21.59
  rectangle net NetC4_2: 9.779,22.098 12.192,24.13
  rectangle net HEATER2: -23.241,-29.083 -21.971,-28.321
  rectangle net HEATER2: -44.577,-23.876 -43.561,-22.352
  rectangle net NetD2_A: -18.415,10.033 -16.891,12.319
  rectangle net NetD2_A: -10.16,13.114 -8.857,15.621
  rectangle net NetD2_A: -16.256,21.082 -14.351,22.987
  rectangle net VCC: 15.621,16.764 19.812,19.05
  rectangle net "CKT GND": 22.479,13.843 25.4,16.002
  rectangle net "CKT GND": 15.621,6.477 18.796,9.017
  rectangle net "CKT GND": 16.256,14.351 18.669,16.002
  rectangle net "CKT GND": 8.509,11.43 12.192,13.843
  rectangle net "CKT GND": 8.382,7.366 12.7,10.541
  rectangle net "CKT GND": 4.191,5.334 6.731,7.874
  rectangle net "CKT GND": -1.905,8.001 0.889,9.906
  rectangle net CHASSIS_GND: -46.101,-10.16 -42.545,-7.112
  rectangle net VCC: 38.862,16.51 42.799,21.844
  rectangle net HEATER2: 34.798,33.02 40.513,36.576
  rectangle net VCC: -34.417,14.351 -32.258,17.018
  rectangle net VEE: 28.194,-15.367 32.893,-11.303
  rectangle net HEATER1: -48.006,-19.939 -43.307,-18.415
  rectangle net HEATER2: -44.45,-27.94 -42.037,-22.733

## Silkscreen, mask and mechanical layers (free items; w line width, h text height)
Top Overlay:
  drawing of 907 lines, arcs and shapes, not listed
  text "15k" at 7.493,31.369 h1.1 r270
  text "0.01/50V" at 16.764,30.861 h1.1 r270
  text "330" at -13.335,28.702 h1.1
  text "1N4007" at 31.496,28.067 h1.1 r270
  text "100k" at -13.462,26.162 h1.1
  text "27k" at -21.336,21.971 h1.1
  text "1N4148" at -24.511,18.415 h1.1
  text "1k" at -1.651,18.161 h1.1 r270
  text "3k9/2W" at 36.322,17.018 h1.1 r270
  text "1N4148" at -24.511,16.383 h1.1
  text "5.1Vz" at 21.59,13.716 h1.1 r270
  text "47uF/16V" at 12.446,11.811 h1.1
  text "360/3W" at 29.083,11.049 h1.1 r270
  text "5.1k" at -23.876,10.414 h1.1
  text "A2804L" at 3.429,10.16 h1.1
  text "RED" at -41.656,8.509 h1.1
  text "0.1/25V" at -8.509,8.255 h1.1
  text "0.1/25V" at -7.493,6.096 h1.1
  text "12k" at 7.493,5.334 h1.1 r270
  text "0.01/25V" at -29.591,1.778 h1.1 r270
  text "47uF/16V" at 11.811,0.889 h1.1
  text "Yellow" at 32.893,-2.54 h1.1
  text "1.8k" at -37.338,-4.191 h1.1
  text "B5K" at -1.397,-4.826 h1.1
  text "5.1Vz" at -10.16,-5.207 h1.1 r270
  text "LM324" at -19.812,-12.192 h1.1
  text "24k" at 1.524,-12.446 h1.1
  text "220uF/50V" at 11.176,-13.462 h1.1
  text "3.0Vz" at -15.113,-15.621 h1.1
  text "130k" at -14.224,-17.272 h1.1
  text "HAKKO 936" at 46.609,-23.749 h2.5 r90
  text "500R" at -1.651,-24.257 h0.9
  text "1M" at -29.591,-26.289 h1.1 r270
  text "0.01/25V" at -20.447,-27.305 h1.1 r270
  text "66.5k" at -22.098,-29.591 h1.1 r270
  text "180k" at -23.749,-29.972 h1.1 r270
  text "1k0" at -25.527,-30.48 h1.1 r270
  text "WWW.SZLCSC.COM" at 14.503,-32.487 h1.78
  text "390" at -0.889,-34.29 h1.1
  text "A1321 HEATER" at -50.673,-34.544 h2
  text "B2319" at 39.751,-34.798 h1.5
